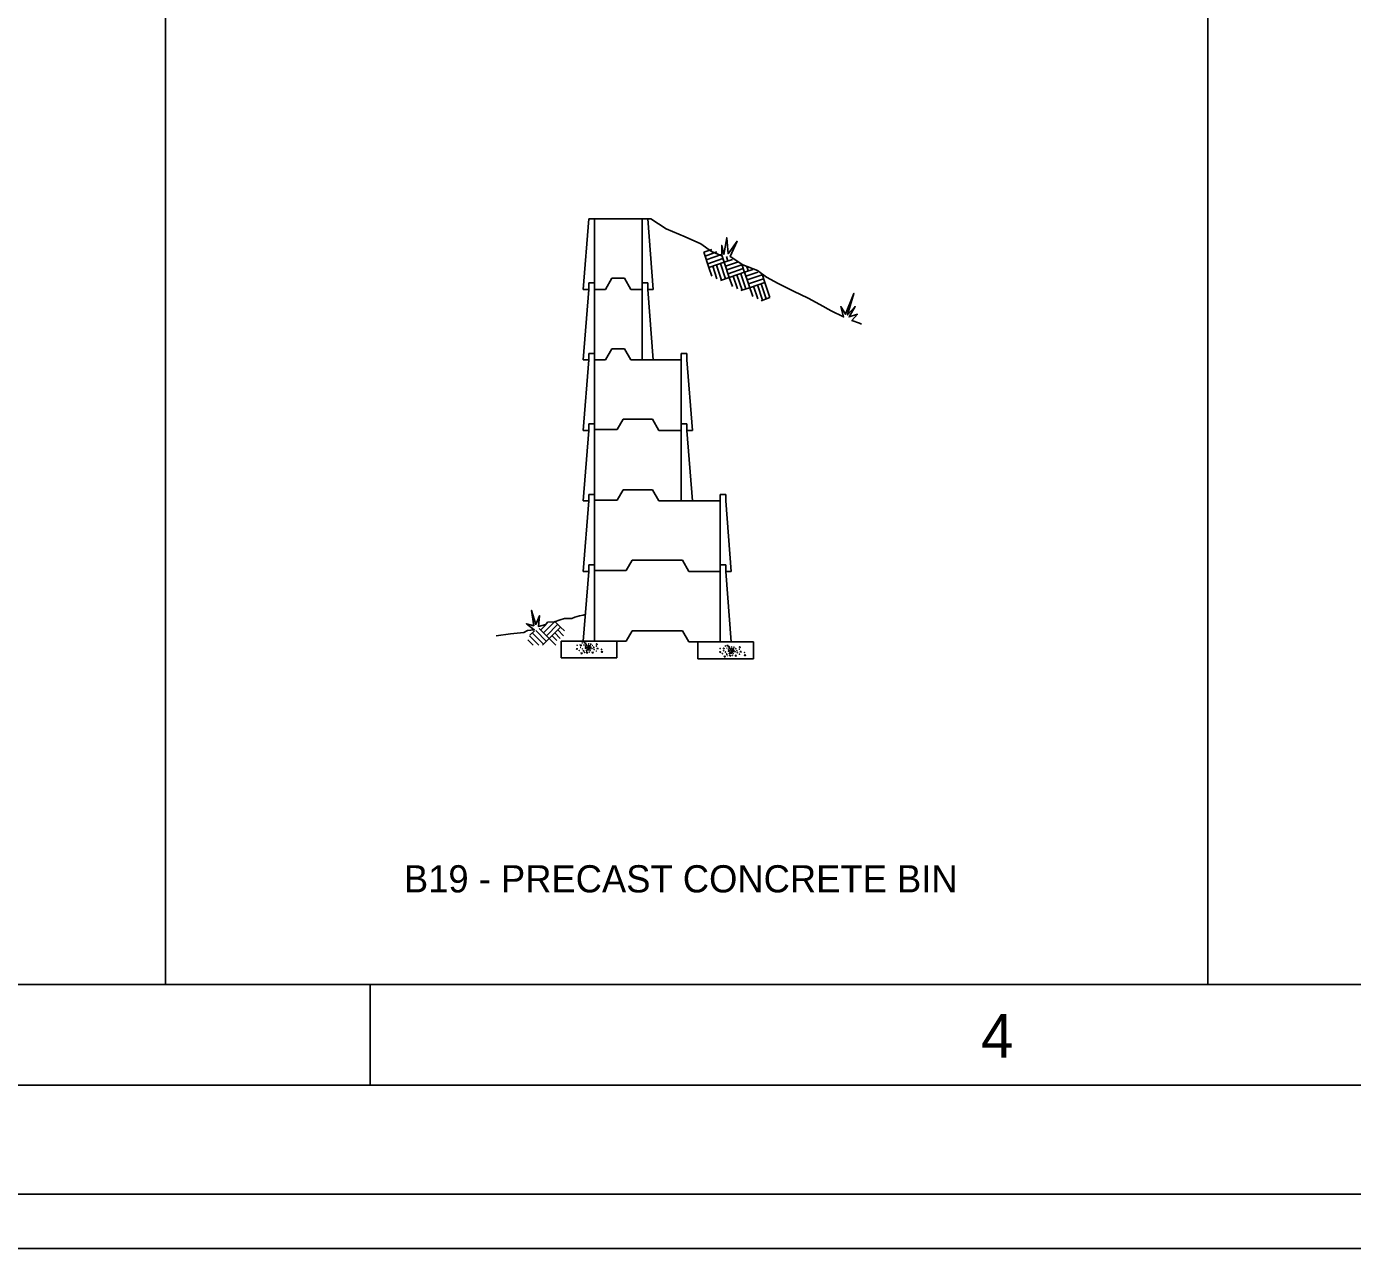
# Model space of a CAD drawing. Extents: x -0.04 to 2.79, y -0.02 to 1.81.
# Drawn here: x 0.466 to 0.974, y -0.021 to 0.447 of the extents above; entities that cross this region are included whole.
import ezdxf

# ---------------------------------------------------------------- set-up
doc = ezdxf.new("R2010")
doc.units = 0
for name, color, linetype in [('G-ANNO-NPLT', 7, 'Continuous'), ('G-ANNO-PLOT', 7, 'Continuous'), ('G-ANNO-TTLB', 7, 'Continuous'), ('Level 1', 7, 'Continuous'), ('Level 2', 7, 'Continuous')]:
    doc.layers.add(name, color=color, linetype=linetype)

msp = doc.modelspace()

# ---------------------------------------------------------------- linework, layer by layer
for p, q in [((0.51951, 1.73185), (0.51951, 0.08028)), ((0.91867, 1.71305), (0.91867, 0.08028))]:
    msp.add_line(p, q)
at = {"layer": 'G-ANNO-NPLT'}
msp.add_lwpolyline([(-0.04167, 1.8125), (2.79167, 1.8125), (2.79167, -0.02083), (-0.04167, -0.02083)], close=True, dxfattribs=at)
at = {"layer": 'G-ANNO-PLOT'}
msp.add_line((2.79167, -0.02083), (-0.04167, -0.02083), dxfattribs=at)
msp.add_lwpolyline([(0, 0), (2.79167, 0), (2.79167, 1.79167), (0, 1.79167)], close=True, dxfattribs=at)
at = {"layer": 'G-ANNO-TTLB'}
msp.add_line((0.59784, 0.04177), (0.59784, 0.08028), dxfattribs=at)
for points in [[(0.08333, 0.04167), (2.72917, 0.04167), (2.72917, 1.75), (0.2515, 1.75)], [(0.11656, 0.08028), (2.69501, 0.08028), (2.69501, 1.71305), (0.11656, 1.71305)]]:
    msp.add_lwpolyline(points, dxfattribs=at)
at = {"layer": 'Level 1'}
for p, q in [((0.67943, 0.34642), (0.68154, 0.37342)), ((0.68154, 0.37342), (0.70506, 0.37342)), ((0.68373, 0.34642), (0.68373, 0.37342)), ((0.70198, 0.34642), (0.70198, 0.37342)), ((0.70629, 0.34642), (0.70417, 0.37342)), ((0.72563, 0.36064), (0.72877, 0.36173)), ((0.72761, 0.35483), (0.72563, 0.36064)), ((0.72611, 0.3592), (0.73069, 0.36077)), ((0.72659, 0.35777), (0.73247, 0.35975)), ((0.72713, 0.35626), (0.73294, 0.35825)), ((0.72761, 0.35483), (0.73342, 0.35681)), ((0.73247, 0.34998), (0.73048, 0.35578)), ((0.73397, 0.35045), (0.73199, 0.35633)), ((0.73342, 0.35681), (0.7324, 0.35995)), ((0.73342, 0.35681), (0.73657, 0.35784)), ((0.73342, 0.35681), (0.73657, 0.35784)), ((0.7354, 0.351), (0.73342, 0.35681)), ((0.7339, 0.35537), (0.73848, 0.35688)), ((0.73486, 0.35729), (0.73431, 0.359)), ((0.73445, 0.35387), (0.74026, 0.35585)), ((0.73636, 0.35777), (0.73629, 0.35797)), ((0.74121, 0.35291), (0.74019, 0.35606)), ((0.68797, 0.34642), (0.69043, 0.35073)), ((0.69043, 0.35073), (0.69528, 0.35073)), ((0.69774, 0.34642), (0.69528, 0.35073)), ((0.72877, 0.35148), (0.72761, 0.35483)), ((0.73069, 0.35052), (0.72905, 0.35531)), ((0.73206, 0.34984), (0.7354, 0.351)), ((0.73493, 0.35244), (0.74074, 0.35442)), ((0.7354, 0.351), (0.74121, 0.35298)), ((0.73657, 0.34758), (0.7354, 0.351)), ((0.73848, 0.34663), (0.73684, 0.35148)), ((0.74033, 0.34615), (0.73834, 0.35196)), ((0.74176, 0.34663), (0.73978, 0.35244)), ((0.74121, 0.35298), (0.74436, 0.35401)), ((0.74121, 0.35298), (0.74436, 0.35401)), ((0.74436, 0.34376), (0.74121, 0.35298)), ((0.74169, 0.35148), (0.74627, 0.35305)), ((0.74272, 0.35346), (0.7421, 0.3551)), ((0.74224, 0.35004), (0.74805, 0.35203)), ((0.74272, 0.34861), (0.74853, 0.35052)), ((0.74415, 0.35394), (0.74409, 0.35414)), ((0.74901, 0.34909), (0.74798, 0.35223)), ((0.67943, 0.34642), (0.68154, 0.34642)), ((0.67943, 0.31942), (0.68154, 0.34642)), ((0.68154, 0.34642), (0.68154, 0.34895)), ((0.68154, 0.34895), (0.68373, 0.34895)), ((0.68373, 0.31942), (0.68373, 0.34642)), ((0.68373, 0.34642), (0.68797, 0.34642)), ((0.69774, 0.34642), (0.70198, 0.34642)), ((0.70417, 0.34895), (0.70198, 0.34895)), ((0.70198, 0.31942), (0.70198, 0.34642)), ((0.70417, 0.34642), (0.70417, 0.34895)), ((0.70629, 0.34642), (0.70417, 0.34642)), ((0.70629, 0.31942), (0.70417, 0.34642)), ((0.73985, 0.34601), (0.7432, 0.3471)), ((0.7432, 0.3471), (0.74901, 0.34909)), ((0.74627, 0.3428), (0.74463, 0.34765)), ((0.74812, 0.34232), (0.74614, 0.34813)), ((0.74955, 0.3428), (0.74757, 0.34861)), ((0.75099, 0.34328), (0.74901, 0.34909)), ((0.74764, 0.34211), (0.75099, 0.34328)), ((0.68154, 0.31942), (0.68154, 0.32195)), ((0.68154, 0.32195), (0.68373, 0.32195)), ((0.68797, 0.31942), (0.69043, 0.32373)), ((0.69043, 0.32373), (0.69528, 0.32373)), ((0.69774, 0.31942), (0.69528, 0.32373)), ((0.71695, 0.29242), (0.71695, 0.32195)), ((0.71914, 0.32195), (0.71695, 0.32195)), ((0.71914, 0.31942), (0.71914, 0.32195)), ((0.67943, 0.31942), (0.68154, 0.31942)), ((0.67943, 0.29242), (0.68154, 0.31942)), ((0.68373, 0.29242), (0.68373, 0.31942)), ((0.68373, 0.31942), (0.68797, 0.31942)), ((0.69774, 0.31942), (0.71695, 0.31942)), ((0.72126, 0.29242), (0.71914, 0.31942)), ((0.68154, 0.29242), (0.68154, 0.29495)), ((0.68154, 0.29495), (0.68373, 0.29495)), ((0.69248, 0.29277), (0.69474, 0.29673)), ((0.69474, 0.29673), (0.70595, 0.29673)), ((0.70841, 0.29242), (0.70595, 0.29673)), ((0.71914, 0.29495), (0.71695, 0.29495)), ((0.71914, 0.29242), (0.71914, 0.29495)), ((0.67943, 0.29242), (0.68154, 0.29242)), ((0.67943, 0.26543), (0.68154, 0.29242)), ((0.68373, 0.29277), (0.69248, 0.29277)), ((0.68373, 0.26543), (0.68373, 0.29242)), ((0.70841, 0.29242), (0.71695, 0.29242)), ((0.71695, 0.26543), (0.71695, 0.29242)), ((0.72126, 0.29242), (0.71914, 0.29242)), ((0.72126, 0.26543), (0.71914, 0.29242)), ((0.69248, 0.26577), (0.69474, 0.26973)), ((0.69474, 0.26973), (0.70595, 0.26973)), ((0.70841, 0.26543), (0.70595, 0.26973)), ((0.67943, 0.26543), (0.68154, 0.26543)), ((0.67943, 0.23843), (0.68154, 0.26543)), ((0.68154, 0.26543), (0.68154, 0.26795)), ((0.68154, 0.26795), (0.68373, 0.26795)), ((0.68373, 0.26577), (0.69248, 0.26577)), ((0.68373, 0.23843), (0.68373, 0.26543)), ((0.70841, 0.26543), (0.73192, 0.26543)), ((0.73192, 0.21143), (0.73192, 0.26795)), ((0.73404, 0.26795), (0.73192, 0.26795)), ((0.73404, 0.26543), (0.73404, 0.26795)), ((0.73616, 0.23843), (0.73404, 0.26543)), ((0.68154, 0.23843), (0.68154, 0.24096)), ((0.68154, 0.24096), (0.68373, 0.24096)), ((0.68373, 0.23877), (0.6959, 0.23877)), ((0.6959, 0.23877), (0.69815, 0.24273)), ((0.69815, 0.24273), (0.7175, 0.24273)), ((0.71996, 0.23843), (0.7175, 0.24273)), ((0.73404, 0.24096), (0.73192, 0.24096)), ((0.73404, 0.23843), (0.73404, 0.24096)), ((0.67943, 0.23843), (0.68154, 0.23843)), ((0.67949, 0.21177), (0.68154, 0.23843)), ((0.68373, 0.21177), (0.68373, 0.23843)), ((0.71996, 0.23843), (0.73192, 0.23843)), ((0.73616, 0.23843), (0.73404, 0.23843)), ((0.73616, 0.21143), (0.73404, 0.23843)), ((0.66425, 0.21491), (0.66863, 0.21922)), ((0.67081, 0.2171), (0.66849, 0.21943)), ((0.66241, 0.2102), (0.65885, 0.21375)), ((0.65899, 0.21403), (0.66077, 0.21573)), ((0.66425, 0.21054), (0.65995, 0.21491)), ((0.66535, 0.21163), (0.66124, 0.2158)), ((0.66897, 0.2102), (0.66261, 0.21655)), ((0.66316, 0.21601), (0.665, 0.21785)), ((0.66535, 0.21382), (0.66972, 0.21819)), ((0.66644, 0.21273), (0.67081, 0.2171)), ((0.66931, 0.21204), (0.66753, 0.21382)), ((0.67068, 0.21279), (0.66863, 0.21491)), ((0.67191, 0.21382), (0.66972, 0.21601)), ((0.67225, 0.21567), (0.67081, 0.2171)), ((0.6959, 0.21177), (0.69815, 0.21573)), ((0.69815, 0.21573), (0.7175, 0.21573)), ((0.71996, 0.21143), (0.7175, 0.21573)), ((0.66029, 0.2102), (0.65824, 0.21225)), ((0.66391, 0.2102), (0.66644, 0.21273)), ((0.67095, 0.21177), (0.6959, 0.21177)), ((0.67095, 0.20534), (0.67095, 0.21177)), ((0.69228, 0.20534), (0.69228, 0.21177)), ((0.71996, 0.21143), (0.7447, 0.21143)), ((0.72337, 0.205), (0.72337, 0.21143)), ((0.7447, 0.205), (0.7447, 0.21143)), ((0.67095, 0.20534), (0.69228, 0.20534)), ((0.72337, 0.205), (0.7447, 0.205))]:
    msp.add_line(p, q, dxfattribs=at)
for points in [[(0.70506, 0.37342), (0.7054, 0.37342), (0.71128, 0.36966), (0.71845, 0.36652), (0.72454, 0.36385), (0.72857, 0.36091), (0.73253, 0.35927), (0.73253, 0.3633), (0.73335, 0.35982), (0.73445, 0.36624), (0.73493, 0.36009), (0.73841, 0.36488), (0.73575, 0.359), (0.74053, 0.35585), (0.74614, 0.35373), (0.74962, 0.35107), (0.75413, 0.34868), (0.75994, 0.34574), (0.76555, 0.34307), (0.77006, 0.34068), (0.77436, 0.33829), (0.77915, 0.33589), (0.77806, 0.33986), (0.77997, 0.33692), (0.78311, 0.34492), (0.78072, 0.33665), (0.78366, 0.33986), (0.78127, 0.33589), (0.78448, 0.33692), (0.78236, 0.33453), (0.7853, 0.3335), (0.78605, 0.33309)], [(0.67512, 0.22045), (0.67225, 0.22045), (0.67068, 0.2199), (0.66842, 0.21915), (0.66582, 0.21895), (0.66507, 0.21813), (0.66227, 0.21737), (0.66275, 0.22148), (0.66124, 0.21813), (0.65967, 0.22353), (0.66049, 0.21765), (0.65769, 0.2184), (0.6607, 0.21608), (0.65817, 0.21587), (0.65666, 0.21505), (0.65154, 0.21457), (0.64614, 0.21382)], [(0.67512, 0.22045), (0.67621, 0.22086), (0.67799, 0.22141), (0.67949, 0.22175), (0.68025, 0.22189)]]:
    msp.add_lwpolyline(points, dxfattribs=at)
at = {"layer": 'Level 2'}
for points in [[(0.67703, 0.20849), (0.6769, 0.20883), (0.67724, 0.20883), (0.67703, 0.20849)], [(0.67847, 0.21047), (0.67833, 0.21013), (0.67867, 0.21006), (0.6784, 0.21047)], [(0.6799, 0.21095), (0.6797, 0.21122), (0.68011, 0.21122), (0.6799, 0.21088)], [(0.68059, 0.21047), (0.68045, 0.21013), (0.68079, 0.21013), (0.68052, 0.21047)], [(0.68052, 0.20801), (0.68072, 0.20828), (0.68079, 0.20808), (0.68052, 0.20801)], [(0.68113, 0.20904), (0.68127, 0.20931), (0.68141, 0.2091), (0.68113, 0.20904)], [(0.68141, 0.20876), (0.6812, 0.20842), (0.68154, 0.20835), (0.68134, 0.20876)], [(0.68182, 0.20979), (0.68202, 0.21006), (0.68209, 0.20986), (0.68182, 0.20979)], [(0.68202, 0.20945), (0.68182, 0.2091), (0.68223, 0.2091), (0.68195, 0.20945)], [(0.68236, 0.21074), (0.68243, 0.21047), (0.68216, 0.21047)], [(0.68216, 0.21054), (0.68236, 0.21068)], [(0.68257, 0.2089), (0.68271, 0.20904), (0.68284, 0.2089), (0.68264, 0.2089)], [(0.68332, 0.20938), (0.68346, 0.20945), (0.68353, 0.20924), (0.68332, 0.20931)], [(0.68462, 0.21088), (0.68448, 0.21054), (0.68483, 0.21054), (0.68455, 0.21088)], [(0.68489, 0.20869), (0.68476, 0.20897), (0.6851, 0.20897), (0.68489, 0.20863)], [(0.73329, 0.20924), (0.73315, 0.2089), (0.73349, 0.2089), (0.73322, 0.20924)], [(0.73472, 0.20979), (0.73452, 0.21006), (0.73493, 0.21006), (0.73472, 0.20972)], [(0.7354, 0.20931), (0.73527, 0.20897), (0.73561, 0.2089), (0.73534, 0.20931)], [(0.73664, 0.20856), (0.73684, 0.2089), (0.73691, 0.20869), (0.73664, 0.20856)], [(0.73684, 0.20828), (0.73664, 0.20794), (0.73705, 0.20787), (0.73677, 0.20828)], [(0.73698, 0.20931), (0.73718, 0.20951)], [(0.73718, 0.20951), (0.73725, 0.20931), (0.73698, 0.20931)], [(0.73944, 0.20972), (0.7393, 0.20938), (0.73964, 0.20931), (0.73937, 0.20972)], [(0.67881, 0.20733), (0.67867, 0.20699), (0.67902, 0.20692), (0.67874, 0.20733)], [(0.67943, 0.20801), (0.67956, 0.20815), (0.6797, 0.20801), (0.67936, 0.20794)], [(0.68086, 0.20712), (0.68066, 0.20746), (0.68107, 0.20746), (0.68086, 0.20705)], [(0.68305, 0.2076), (0.68291, 0.20726), (0.68325, 0.20726), (0.68298, 0.2076)], [(0.6866, 0.20787), (0.6864, 0.20753), (0.68681, 0.20746), (0.68653, 0.20787)], [(0.73185, 0.20733), (0.73171, 0.2076), (0.73206, 0.2076), (0.73185, 0.20726)], [(0.73363, 0.2061), (0.73349, 0.20575), (0.73383, 0.20575), (0.73356, 0.2061)], [(0.73424, 0.20678), (0.73438, 0.20692), (0.73452, 0.20678), (0.73417, 0.20678)], [(0.73534, 0.20678), (0.73554, 0.20712), (0.73561, 0.20692), (0.73534, 0.20678)], [(0.73568, 0.20596), (0.73547, 0.20623), (0.73588, 0.20623), (0.73568, 0.20589)], [(0.73595, 0.20781), (0.73609, 0.20808), (0.73622, 0.20787), (0.73595, 0.20781)], [(0.73622, 0.20753), (0.73602, 0.20719), (0.73636, 0.20719), (0.73616, 0.20753)], [(0.73739, 0.20767), (0.73752, 0.20787), (0.73766, 0.20767), (0.73746, 0.20767)], [(0.73787, 0.20644), (0.73773, 0.2061), (0.73807, 0.20603), (0.7378, 0.20644)], [(0.73814, 0.20815), (0.73828, 0.20822), (0.73834, 0.20801), (0.73814, 0.20815)], [(0.73971, 0.20746), (0.73957, 0.20774), (0.73992, 0.20774), (0.73971, 0.2074)], [(0.74142, 0.20664), (0.74121, 0.2063), (0.74162, 0.2063), (0.74135, 0.20664)]]:
    msp.add_lwpolyline(points, dxfattribs=at)
for centre in [(0.67711, 0.21016), (0.67847, 0.2093), (0.6791, 0.21107), (0.67913, 0.20878), (0.67976, 0.21024), (0.68031, 0.20958), (0.68031, 0.20903), (0.68056, 0.21084), (0.68073, 0.2092), (0.6809, 0.20869), (0.68117, 0.20964), (0.68151, 0.2101), (0.68154, 0.2107), (0.68168, 0.20947), (0.68177, 0.20886), (0.68203, 0.20872), (0.68237, 0.20947), (0.68309, 0.21007), (0.68367, 0.20852), (0.6845, 0.20987), (0.68649, 0.20858), (0.73189, 0.20896), (0.73388, 0.20988), (0.73454, 0.20905), (0.73509, 0.20838), (0.73534, 0.20965), (0.73595, 0.20844), (0.73629, 0.2089), (0.73632, 0.2095), (0.73646, 0.20827), (0.73716, 0.20827), (0.73787, 0.20887), (0.73928, 0.20867), (0.67795, 0.20814), (0.67993, 0.20745), (0.68177, 0.20754), (0.68212, 0.20817), (0.68453, 0.20791), (0.73273, 0.20695), (0.73325, 0.2081), (0.73391, 0.20758), (0.73471, 0.20625), (0.73509, 0.20784), (0.73552, 0.20801), (0.73569, 0.20749), (0.73655, 0.20766), (0.73656, 0.20634), (0.73681, 0.20752), (0.7369, 0.20697), (0.73845, 0.20732), (0.73932, 0.20672), (0.74127, 0.20738)]:
    msp.add_circle(centre, 0.0000555, dxfattribs=at)

# ---------------------------------------------------------------- texts
msp.add_text('B19 - PRECAST CONCRETE BIN', height=0.0104167).set_placement((0.61077, 0.11552))
at = {"layer": 'G-ANNO-TTLB'}
msp.add_text('4', height=0.01667, dxfattribs=at).set_placement((0.83187, 0.05228))

doc.saveas('drawing.dxf')
